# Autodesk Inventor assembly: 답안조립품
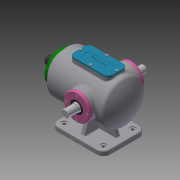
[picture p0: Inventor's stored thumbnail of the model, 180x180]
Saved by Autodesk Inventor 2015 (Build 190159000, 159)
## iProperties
Created: 2021-11
Part Number: 답안조립품
Document SubType Name: Assembly
Designer: 10259o
Author: 10259o
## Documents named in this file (14)
- C:\Users\10259o\Desktop\711106V1019\답안조립품.iam
- C:\Users\10259o\Desktop\711106V1019\베어링 6205.ipt
- 베어링 6205.ipt
- C:\Users\10259o\Desktop\711106V1019\본체.ipt
- C:\Users\10259o\Desktop\711106V1019\볼트 M4x0.7.ipt
- C:\Users\10259o\Desktop\711106V1019\부시.ipt
- C:\Users\10259o\Desktop\711106V1019\상부커버.ipt
- C:\Users\10259o\Desktop\711106V1019\슬라이드 커버.ipt
- C:\Users\10259o\Desktop\711106V1019\슬라이드.ipt
- C:\Users\10259o\Desktop\711106V1019\오일실.ipt
- 오일실.ipt
- C:\Users\10259o\Desktop\711106V1019\육각머리볼트 M4.ipt
- C:\Users\10259o\Desktop\711106V1019\축 커버.ipt
- C:\Users\10259o\Desktop\711106V1019\편심축.ipt
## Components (12 placed, 1 different names)
1. M4x0.7:1
2. M4x0.7:3
3. M4x0.7:4
4. M4x0.7:5
5. M4x0.7:2
6. M4x0.7:6
7. M4x0.7:7
8. M4x0.7:8
9. M4x0.7:9
10. M4x0.7:10
11. M4x0.7:11
12. M4x0.7:12
## Named parameters: d3_d2 = 0, d4_d1 = 0
